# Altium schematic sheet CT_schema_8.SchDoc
size 391 x 238 mm
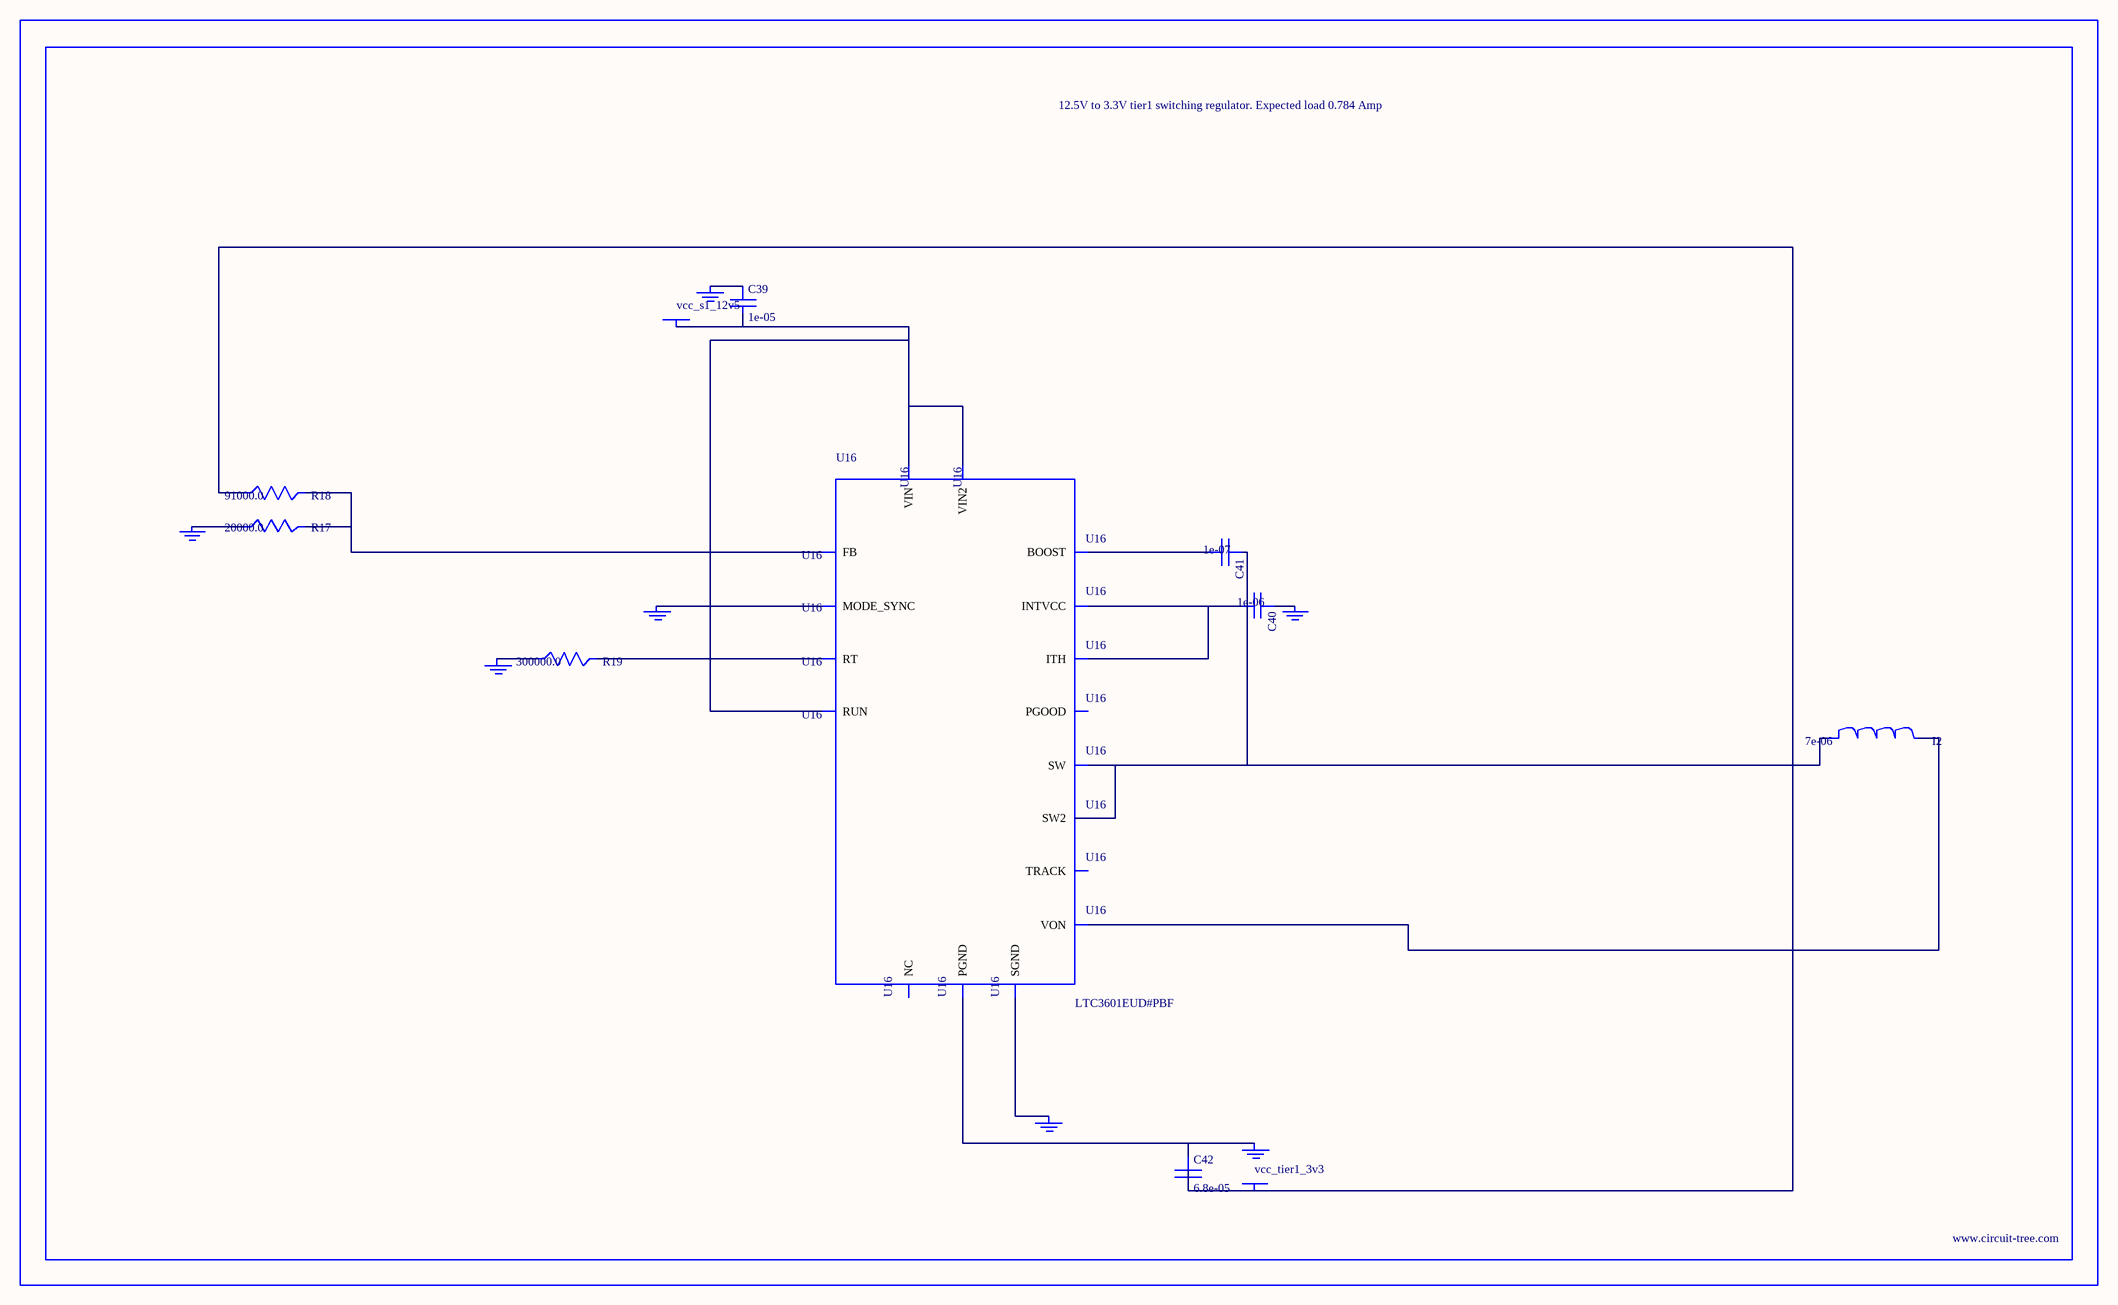
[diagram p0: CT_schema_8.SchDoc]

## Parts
BORDER7  (no value)
C39  1e-05  [C0805]
C40  1e-06  [C0603]
C41  1e-07  [C0402]
C42  6.8e-05  [2220]
GND_INSTANCE_7_0  (no value)
GND_INSTANCE_7_1  (no value)
GND_INSTANCE_7_2  (no value)
GND_INSTANCE_7_3  (no value)
GND_INSTANCE_7_4  (no value)
GND_INSTANCE_7_5  (no value)
GND_INSTANCE_7_6  (no value)
I2  7e-06  [DR1040]
POWER_INSTANCE_7_0  vcc_s1_12v5
POWER_INSTANCE_7_1  vcc_tier1_3v3
R17  20000.0  [R0603]
R18  91000.0  [R0603]
R19  300000.0  [R0603]
U16  LTC3601EUD#PBF  [QFN-16_EP]

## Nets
NetC39_1: C39.1 GND_INSTANCE_7_5.0(GND)
NetC39_2: C39.2 POWER_INSTANCE_7_0.0(PWR) U16.14(RUN) U16.15(VIN) U16.16(VIN2)
NetC40_1: C40.1 GND_INSTANCE_7_1.0(GND)
NetC40_2: C40.2 U16.7(INTVCC) U16.12(ITH)
NetC41_1: C41.1 I2.1 U16.3(SW) U16.4(SW2)
NetC41_2: C41.2 U16.6(BOOST)
NetC42_1: C42.1 GND_INSTANCE_7_6.0(GND) U16.17(PGND)
NetC42_2: C42.2 I2.2 POWER_INSTANCE_7_1.0(PWR) R18.1 U16.8(VON)
NetGND_INSTANCE_7_0_0: GND_INSTANCE_7_0.0(GND) U16.1(MODE_SYNC)
NetGND_INSTANCE_7_2_0: GND_INSTANCE_7_2.0(GND) U16.9(SGND)
NetGND_INSTANCE_7_3_0: GND_INSTANCE_7_3.0(GND) R19.1
NetGND_INSTANCE_7_4_0: GND_INSTANCE_7_4.0(GND) R17.1
NetR17_2: R17.2 R18.2 U16.11(FB)
NetR19_2: R19.2 U16.10(RT)

Not connected (* = marked no-connect by the designer): U16 2(PGOOD) 5(NC) 13(TRACK)

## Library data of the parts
BORDER7 = BORDER_PAGE7
C39 = C0805C106K8RACTU
C40 = C0603C105K3RACTU
C41 = C0402C104K3RACTU
C42 = C5750X5R1A686M
GND_INSTANCE_7_0-GND_INSTANCE_7_6 = GND
I2 = DR1040-7R0-R
POWER_INSTANCE_7_0 POWER_INSTANCE_7_1 = PWR
R17 = RC0603JR-0720KL
R18 = RC0603JR-0791KL
R19 = RC0603JR-07300KL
